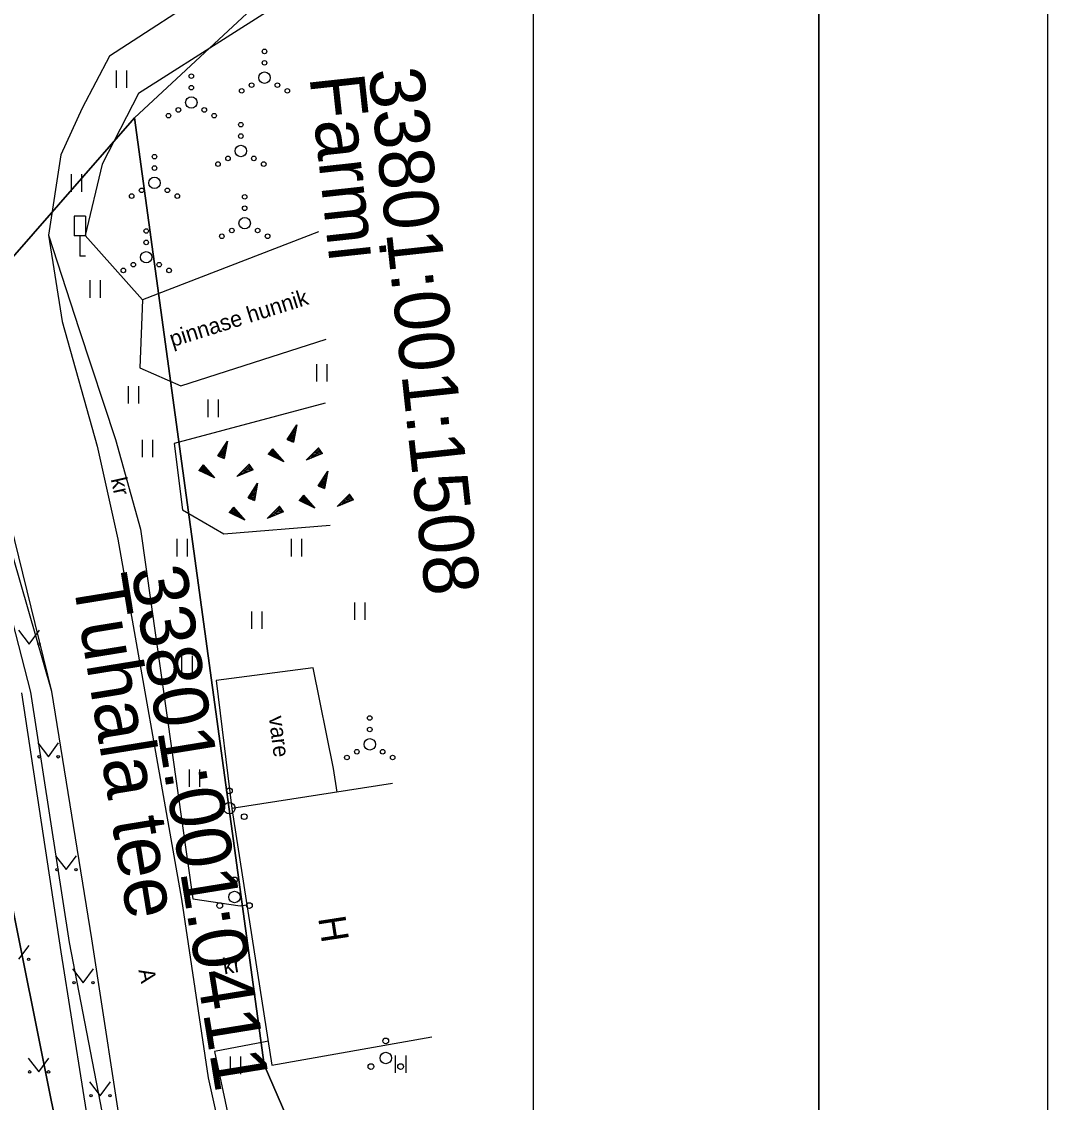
# Model space of a CAD drawing. Extents: x 554947 to 555436, y 6564938 to 6565792.
# Drawn here: x 555348.19 to 555393.07, y 6565480.81 to 6565528.08 of the extents above; entities that cross this region are included whole.
import ezdxf

# ---------------------------------------------------------------- set-up
doc = ezdxf.new("R2010")
doc.units = 0
for name, color, linetype in [('AED', 7, 'Continuous'), ('HALJASTUS', 7, 'Continuous'), ('HOONE', 7, 'Continuous'), ('LIIKLUS', 7, 'Continuous'), ('PIIR', 7, 'Continuous'), ('PR_SIDE', 7, 'Continuous'), ('PUU', 7, 'Continuous'), ('RELJEEF', 7, 'Continuous'), ('TEE', 7, 'Continuous'), ('VORMISTUS_3', 7, 'Continuous')]:
    doc.layers.add(name, color=color, linetype=linetype)

msp = doc.modelspace()

# ---------------------------------------------------------------- linework, layer by layer
at = {"layer": 'AED'}
msp.add_lwpolyline([(555353.187, 6565471.073), (555351.365, 6565478.297), (555349.912, 6565487.399), (555348.203, 6565498.717)], dxfattribs=at)
at = {"layer": 'HALJASTUS'}
for p, q in [((555352.324, 6565525.945), (555352.324, 6565525.183)), ((555352.779, 6565525.945), (555352.779, 6565525.183)), ((555350.36, 6565521.402), (555350.36, 6565520.641)), ((555350.815, 6565521.402), (555350.815, 6565520.641)), ((555351.166, 6565516.766), (555351.166, 6565516.005)), ((555351.621, 6565516.766), (555351.621, 6565516.005)), ((555361.091, 6565513.097), (555361.091, 6565512.335)), ((555361.546, 6565513.097), (555361.546, 6565512.335)), ((555352.843, 6565512.14), (555352.843, 6565511.379)), ((555353.298, 6565512.14), (555353.298, 6565511.379)), ((555356.338, 6565511.545), (555356.338, 6565510.783)), ((555356.793, 6565511.545), (555356.793, 6565510.783)), ((555353.46, 6565509.792), (555353.46, 6565509.031)), ((555353.915, 6565509.792), (555353.915, 6565509.031)), ((555354.98, 6565505.45), (555354.98, 6565504.689)), ((555355.435, 6565505.45), (555355.435, 6565504.689)), ((555359.98, 6565505.45), (555359.98, 6565504.689)), ((555360.435, 6565505.45), (555360.435, 6565504.689)), ((555362.751, 6565502.676), (555362.751, 6565501.915)), ((555363.206, 6565502.676), (555363.206, 6565501.915)), ((555358.242, 6565502.281), (555358.242, 6565501.52)), ((555358.697, 6565502.281), (555358.697, 6565501.52)), ((555348.055, 6565501.461), (555348.518, 6565500.854)), ((555348.518, 6565500.854), (555348.964, 6565501.461)), ((555355.188, 6565500.335), (555355.188, 6565499.574)), ((555355.643, 6565500.335), (555355.643, 6565499.574)), ((555348.895, 6565496.532), (555349.359, 6565495.925)), ((555349.359, 6565495.925), (555349.804, 6565496.532)), ((555355.523, 6565495.364), (555355.523, 6565494.603)), ((555355.978, 6565495.364), (555355.978, 6565494.603)), ((555349.676, 6565491.594), (555350.14, 6565490.987)), ((555350.14, 6565490.987), (555350.585, 6565491.594)), ((555348.068, 6565487.065), (555348.514, 6565487.672)), ((555350.42, 6565486.649), (555350.883, 6565486.043)), ((555350.883, 6565486.043), (555351.329, 6565486.649)), ((555348.474, 6565482.748), (555348.938, 6565482.141)), ((555348.938, 6565482.141), (555349.383, 6565482.748)), ((555357.313, 6565482.807), (555357.313, 6565482.046)), ((555357.768, 6565482.807), (555357.768, 6565482.046)), ((555364.538, 6565482.859), (555364.538, 6565482.097)), ((555364.993, 6565482.859), (555364.993, 6565482.097)), ((555351.163, 6565481.705), (555351.627, 6565481.098)), ((555351.627, 6565481.098), (555352.072, 6565481.705))]:
    msp.add_line(p, q, dxfattribs=at)
for points in [[(555361.377, 6565530.075), (555353.295, 6565524.933), (555351.719, 6565521.845), (555350.973, 6565518.729), (555353.476, 6565515.91)], [(555361.179, 6565518.885), (555353.476, 6565515.91), (555353.355, 6565512.94), (555355.161, 6565512.154), (555361.518, 6565514.185)]]:
    msp.add_lwpolyline(points, dxfattribs=at)
for centre, radius in [((555358.816, 6565526.776), 0.1), ((555358.816, 6565526.276), 0.1), ((555355.614, 6565525.692), 0.1), ((555358.816, 6565525.626), 0.25), ((555355.614, 6565525.192), 0.1), ((555357.816, 6565525.051), 0.1), ((555358.251, 6565525.301), 0.1), ((555359.381, 6565525.301), 0.1), ((555359.816, 6565525.051), 0.1), ((555355.614, 6565524.542), 0.25), ((555355.049, 6565524.217), 0.1), ((555356.179, 6565524.217), 0.1), ((555354.614, 6565523.967), 0.1), ((555356.614, 6565523.967), 0.1), ((555357.781, 6565523.572), 0.1), ((555357.781, 6565523.072), 0.1), ((555357.781, 6565522.422), 0.25), ((555354.001, 6565522.174), 0.1), ((555357.216, 6565522.097), 0.1), ((555358.346, 6565522.097), 0.1), ((555354.001, 6565521.674), 0.1), ((555356.781, 6565521.847), 0.1), ((555358.781, 6565521.847), 0.1), ((555354.001, 6565521.024), 0.25), ((555353.436, 6565520.699), 0.1), ((555354.566, 6565520.699), 0.1), ((555353.001, 6565520.449), 0.1), ((555355.001, 6565520.449), 0.1), ((555357.949, 6565520.416), 0.1), ((555357.949, 6565519.916), 0.1), ((555357.949, 6565519.266), 0.25), ((555353.64, 6565518.922), 0.1), ((555357.384, 6565518.941), 0.1), ((555358.514, 6565518.941), 0.1), ((555353.64, 6565518.422), 0.1), ((555356.949, 6565518.691), 0.1), ((555358.949, 6565518.691), 0.1), ((555353.64, 6565517.772), 0.25), ((555353.075, 6565517.447), 0.1), ((555354.205, 6565517.447), 0.1), ((555352.64, 6565517.197), 0.1), ((555354.64, 6565517.197), 0.1), ((555348.946, 6565500.854), 0.055), ((555363.421, 6565497.618), 0.1), ((555363.421, 6565497.118), 0.1), ((555363.421, 6565496.468), 0.25), ((555362.856, 6565496.143), 0.1), ((555363.986, 6565496.143), 0.1), ((555348.958, 6565495.925), 0.055), ((555349.787, 6565495.925), 0.055), ((555362.421, 6565495.893), 0.1), ((555364.421, 6565495.893), 0.1), ((555349.739, 6565490.987), 0.055), ((555350.567, 6565490.987), 0.055), ((555348.496, 6565487.065), 0.055), ((555350.482, 6565486.043), 0.055), ((555351.311, 6565486.043), 0.055), ((555348.537, 6565482.141), 0.055), ((555349.366, 6565482.141), 0.055), ((555351.225, 6565481.098), 0.055), ((555352.054, 6565481.098), 0.055)]:
    msp.add_circle(centre, radius, dxfattribs=at)
at = {"layer": 'HOONE'}
for points in [[(555361.999, 6565494.379), (555361.839, 6565495.408), (555360.949, 6565499.816), (555356.698, 6565499.263), (555357.386, 6565493.662)], [(555364.41, 6565494.754), (555357.386, 6565493.662), (555359.132, 6565482.428), (555366.132, 6565483.677)]]:
    msp.add_lwpolyline(points, dxfattribs=at)
at = {"layer": 'LIIKLUS'}
for p, q in [((555350.488, 6565519.566), (555350.488, 6565518.716)), ((555350.988, 6565519.566), (555350.488, 6565519.566)), ((555350.988, 6565519.566), (555350.988, 6565518.716)), ((555350.988, 6565518.716), (555350.488, 6565518.716)), ((555350.738, 6565518.716), (555350.738, 6565517.816)), ((555350.988, 6565517.816), (555350.738, 6565517.816))]:
    msp.add_line(p, q, dxfattribs=at)
at = {"layer": 'PIIR'}
for points in [[(555393.069, 6565560.972), (555353.12, 6565523.87), (555343.14, 6565512.46), (555302.6, 6565539.71), (555242.37, 6565583.94), (555179.42, 6565586.32), (555138.98, 6565580.6), (555121.18, 6565602.26), (555116.17, 6565610.5), (555109.96, 6565624.83), (555093.56, 6565628.47), (555079.04, 6565618.4), (555074.13, 6565607.82), (555075.34, 6565593.24), (555091.74, 6565551.94), (555171.91, 6565394.64), (555191.35, 6565341.19), (555195.08, 6565294.61), (555195.28, 6565271.63), (555191.64, 6565237.48)], [(555393.069, 6565456.052), (555368.05, 6565461.11), (555358.8, 6565482.45), (555353.12, 6565523.87), (555393.069, 6565560.972)], [(555393.069, 6565443.872), (555367.06, 6565449.68), (555351.96, 6565468.55), (555343.14, 6565512.46), (555353.12, 6565523.87), (555358.8, 6565482.45), (555368.05, 6565461.11), (555393.069, 6565454.923)]]:
    msp.add_lwpolyline(points, dxfattribs=at)
msp.add_lwpolyline([(555319.44, 6565481.04), (555343.14, 6565512.46), (555351.96, 6565468.55), (555367.06, 6565449.68), (555367.76, 6565374.28), (555361.76, 6565374.07), (555316.84, 6565372.52), (555312.9, 6565433.84), (555323.07, 6565461.26)], close=True, dxfattribs=at)
at = {"layer": 'PR_SIDE'}
msp.add_lwpolyline([(555383.069, 6565448.914), (555372.326, 6565450.448), (555366.015, 6565452.342), (555363.26, 6565453.626), (555360.292, 6565456.785), (555356.82, 6565461.856), (555354.197, 6565468.745), (555353.746, 6565469.93), (555350.28, 6565487.806), (555348.596, 6565498.754), (555346.199, 6565508), (555346.027, 6565508.326), (555343.44, 6565510.968), (555340.158, 6565515.387), (555337.344, 6565518), (555334.369, 6565519.783), (555331.518, 6565521.47), (555329.521, 6565522.71), (555323.586, 6565526.187), (555323.123, 6565526.49), (555319.055, 6565529.304), (555309.687, 6565535.684), (555309.355, 6565535.944), (555304.351, 6565539.861)], dxfattribs=at)
at = {"layer": 'PUU'}
for centre, radius in [((555357.278, 6565494.429), 0.125), ((555357.278, 6565493.679), 0.25), ((555356.628, 6565493.304), 0.125), ((555357.928, 6565493.304), 0.125), ((555357.506, 6565490.54), 0.125), ((555357.506, 6565489.79), 0.25), ((555356.856, 6565489.415), 0.125), ((555358.156, 6565489.415), 0.125), ((555364.12, 6565483.497), 0.125), ((555364.12, 6565482.747), 0.25), ((555363.47, 6565482.372), 0.125), ((555364.77, 6565482.372), 0.125)]:
    msp.add_circle(centre, radius, dxfattribs=at)
at = {"layer": 'RELJEEF'}
for p, q in [((555359.803, 6565509.798), (555360.223, 6565510.438)), ((555360.223, 6565510.438), (555360.083, 6565509.683)), ((555360.198, 6565510.398), (555360.218, 6565510.408)), ((555359.803, 6565509.798), (555360.128, 6565509.938)), ((555359.853, 6565509.873), (555360.138, 6565509.993)), ((555359.903, 6565509.948), (555360.153, 6565510.053)), ((555359.953, 6565510.023), (555360.078, 6565510.078)), ((555360.003, 6565510.098), (555360.173, 6565510.173)), ((555360.053, 6565510.173), (555360.183, 6565510.233)), ((555360.078, 6565510.078), (555360.163, 6565510.113)), ((555360.098, 6565510.248), (555360.198, 6565510.288)), ((555360.148, 6565510.323), (555360.208, 6565510.348)), ((555356.77, 6565509.089), (555357.19, 6565509.729)), ((555356.97, 6565509.389), (555357.14, 6565509.464)), ((555357.02, 6565509.464), (555357.15, 6565509.524)), ((555357.19, 6565509.729), (555357.05, 6565508.974)), ((555357.065, 6565509.539), (555357.165, 6565509.579)), ((555357.115, 6565509.614), (555357.175, 6565509.639)), ((555357.165, 6565509.689), (555357.185, 6565509.699)), ((555359.803, 6565509.798), (555360.083, 6565509.683)), ((555359.803, 6565509.798), (555359.803, 6565509.798)), ((555359.868, 6565509.773), (555360.118, 6565509.878)), ((555359.933, 6565509.743), (555360.108, 6565509.818)), ((555360.003, 6565509.718), (555360.098, 6565509.758)), ((555360.068, 6565509.693), (555360.083, 6565509.698)), ((555360.641, 6565508.892), (555361.181, 6565509.437)), ((555361.351, 6565509.187), (555361.181, 6565509.437)), ((555356.77, 6565509.089), (555357.095, 6565509.229)), ((555356.77, 6565509.089), (555357.05, 6565508.974)), ((555356.77, 6565509.089), (555356.77, 6565509.089)), ((555356.82, 6565509.164), (555357.105, 6565509.284)), ((555356.835, 6565509.064), (555357.085, 6565509.169)), ((555356.87, 6565509.239), (555357.12, 6565509.344)), ((555356.9, 6565509.034), (555357.075, 6565509.109)), ((555356.92, 6565509.314), (555357.045, 6565509.369)), ((555356.97, 6565509.009), (555357.065, 6565509.049)), ((555357.035, 6565508.984), (555357.05, 6565508.989)), ((555357.045, 6565509.369), (555357.13, 6565509.404)), ((555359.162, 6565509.397), (555358.977, 6565509.157)), ((555359.667, 6565508.827), (555358.977, 6565509.157)), ((555358.987, 6565509.172), (555358.992, 6565509.152)), ((555359.032, 6565509.227), (555359.047, 6565509.127)), ((555359.077, 6565509.287), (555359.102, 6565509.102)), ((555359.117, 6565509.342), (555359.152, 6565509.072)), ((555359.162, 6565509.397), (555359.667, 6565508.827)), ((555359.162, 6565509.397), (555359.207, 6565509.047)), ((555359.162, 6565509.397), (555359.162, 6565509.397)), ((555359.222, 6565509.332), (555359.262, 6565509.022)), ((555359.282, 6565509.262), (555359.317, 6565508.997)), ((555359.342, 6565509.197), (555359.357, 6565509.057)), ((555359.357, 6565509.057), (555359.372, 6565508.967)), ((555359.397, 6565509.127), (555359.427, 6565508.942)), ((555359.457, 6565509.062), (555359.477, 6565508.917)), ((555359.517, 6565508.992), (555359.532, 6565508.892)), ((555361.351, 6565509.187), (555360.641, 6565508.892)), ((555360.851, 6565508.977), (555360.746, 6565508.997)), ((555360.931, 6565509.012), (555360.791, 6565509.042)), ((555361.016, 6565509.047), (555360.831, 6565509.082)), ((555360.966, 6565509.107), (555360.876, 6565509.127)), ((555361.181, 6565509.117), (555360.916, 6565509.167)), ((555361.266, 6565509.152), (555360.961, 6565509.212)), ((555361.101, 6565509.082), (555360.966, 6565509.107)), ((555361.351, 6565509.187), (555361.001, 6565509.252)), ((555361.311, 6565509.242), (555361.046, 6565509.297)), ((555361.271, 6565509.302), (555361.086, 6565509.337)), ((555361.231, 6565509.362), (555361.131, 6565509.382)), ((555361.191, 6565509.422), (555361.171, 6565509.422)), ((555361.351, 6565509.187), (555361.351, 6565509.187)), ((555356.128, 6565508.688), (555355.943, 6565508.448)), ((555355.998, 6565508.518), (555356.013, 6565508.418)), ((555356.043, 6565508.578), (555356.068, 6565508.393)), ((555356.083, 6565508.633), (555356.118, 6565508.363)), ((555356.128, 6565508.688), (555356.633, 6565508.118)), ((555356.128, 6565508.688), (555356.173, 6565508.338)), ((555356.128, 6565508.688), (555356.128, 6565508.688)), ((555356.188, 6565508.623), (555356.228, 6565508.313)), ((555356.248, 6565508.553), (555356.283, 6565508.288)), ((555356.308, 6565508.488), (555356.323, 6565508.348)), ((555357.608, 6565508.183), (555358.148, 6565508.728)), ((555358.233, 6565508.443), (555357.928, 6565508.503)), ((555358.318, 6565508.478), (555357.968, 6565508.543)), ((555358.278, 6565508.533), (555358.013, 6565508.588)), ((555358.238, 6565508.593), (555358.053, 6565508.628)), ((555358.198, 6565508.653), (555358.098, 6565508.673)), ((555358.158, 6565508.713), (555358.138, 6565508.713)), ((555358.318, 6565508.478), (555358.148, 6565508.728)), ((555359.577, 6565508.927), (555359.587, 6565508.862)), ((555359.637, 6565508.857), (555359.642, 6565508.837)), ((555360.681, 6565508.907), (555360.666, 6565508.912)), ((555360.766, 6565508.942), (555360.706, 6565508.957)), ((555356.633, 6565508.118), (555355.943, 6565508.448)), ((555355.953, 6565508.463), (555355.958, 6565508.443)), ((555356.323, 6565508.348), (555356.338, 6565508.258)), ((555356.363, 6565508.418), (555356.393, 6565508.233)), ((555356.423, 6565508.353), (555356.443, 6565508.208)), ((555356.483, 6565508.283), (555356.498, 6565508.183)), ((555356.543, 6565508.218), (555356.553, 6565508.153)), ((555356.603, 6565508.148), (555356.608, 6565508.128)), ((555358.318, 6565508.478), (555357.608, 6565508.183)), ((555357.648, 6565508.198), (555357.633, 6565508.203)), ((555357.733, 6565508.233), (555357.673, 6565508.248)), ((555357.818, 6565508.268), (555357.713, 6565508.288)), ((555357.898, 6565508.303), (555357.758, 6565508.333)), ((555357.983, 6565508.338), (555357.798, 6565508.373)), ((555357.933, 6565508.398), (555357.843, 6565508.418)), ((555358.148, 6565508.408), (555357.883, 6565508.458)), ((555358.068, 6565508.373), (555357.933, 6565508.398)), ((555358.318, 6565508.478), (555358.318, 6565508.478)), ((555361.161, 6565507.771), (555361.581, 6565508.411)), ((555361.261, 6565507.921), (555361.511, 6565508.026)), ((555361.311, 6565507.996), (555361.436, 6565508.051)), ((555361.361, 6565508.071), (555361.531, 6565508.146)), ((555361.411, 6565508.146), (555361.541, 6565508.206)), ((555361.436, 6565508.051), (555361.521, 6565508.086)), ((555361.581, 6565508.411), (555361.441, 6565507.656)), ((555361.456, 6565508.221), (555361.556, 6565508.261)), ((555361.506, 6565508.296), (555361.566, 6565508.321)), ((555361.556, 6565508.371), (555361.576, 6565508.381)), ((555358.094, 6565507.249), (555358.514, 6565507.889)), ((555358.294, 6565507.549), (555358.464, 6565507.624)), ((555358.344, 6565507.624), (555358.474, 6565507.684)), ((555358.369, 6565507.529), (555358.454, 6565507.564)), ((555358.514, 6565507.889), (555358.374, 6565507.134)), ((555358.389, 6565507.699), (555358.489, 6565507.739)), ((555358.439, 6565507.774), (555358.499, 6565507.799)), ((555358.489, 6565507.849), (555358.509, 6565507.859)), ((555361.161, 6565507.771), (555361.486, 6565507.911)), ((555361.161, 6565507.771), (555361.441, 6565507.656)), ((555361.161, 6565507.771), (555361.161, 6565507.771)), ((555361.211, 6565507.846), (555361.496, 6565507.966)), ((555361.226, 6565507.746), (555361.476, 6565507.851)), ((555361.291, 6565507.716), (555361.466, 6565507.791)), ((555361.361, 6565507.691), (555361.456, 6565507.731)), ((555361.426, 6565507.666), (555361.441, 6565507.671)), ((555358.094, 6565507.249), (555358.419, 6565507.389)), ((555358.094, 6565507.249), (555358.374, 6565507.134)), ((555358.094, 6565507.249), (555358.094, 6565507.249)), ((555358.144, 6565507.324), (555358.429, 6565507.444)), ((555358.159, 6565507.224), (555358.409, 6565507.329)), ((555358.194, 6565507.399), (555358.444, 6565507.504)), ((555358.224, 6565507.194), (555358.399, 6565507.269)), ((555358.244, 6565507.474), (555358.369, 6565507.529)), ((555358.294, 6565507.169), (555358.389, 6565507.209)), ((555358.359, 6565507.144), (555358.374, 6565507.149)), ((555360.519, 6565507.37), (555360.334, 6565507.13)), ((555361.024, 6565506.8), (555360.334, 6565507.13)), ((555360.344, 6565507.145), (555360.349, 6565507.125)), ((555360.389, 6565507.2), (555360.404, 6565507.1)), ((555360.434, 6565507.26), (555360.459, 6565507.075)), ((555360.474, 6565507.315), (555360.509, 6565507.045)), ((555360.519, 6565507.37), (555361.024, 6565506.8)), ((555360.519, 6565507.37), (555360.564, 6565507.02)), ((555360.519, 6565507.37), (555360.519, 6565507.37)), ((555360.579, 6565507.305), (555360.619, 6565506.995)), ((555360.639, 6565507.235), (555360.674, 6565506.97)), ((555360.699, 6565507.17), (555360.714, 6565507.03)), ((555360.754, 6565507.1), (555360.784, 6565506.915)), ((555361.998, 6565506.865), (555362.538, 6565507.41)), ((555362.708, 6565507.16), (555361.998, 6565506.865)), ((555362.323, 6565507.08), (555362.233, 6565507.1)), ((555362.538, 6565507.09), (555362.273, 6565507.14)), ((555362.623, 6565507.125), (555362.318, 6565507.185)), ((555362.458, 6565507.055), (555362.323, 6565507.08)), ((555362.708, 6565507.16), (555362.358, 6565507.225)), ((555362.668, 6565507.215), (555362.403, 6565507.27)), ((555362.628, 6565507.275), (555362.443, 6565507.31)), ((555362.588, 6565507.335), (555362.488, 6565507.355)), ((555362.548, 6565507.395), (555362.528, 6565507.395)), ((555362.708, 6565507.16), (555362.538, 6565507.41)), ((555362.708, 6565507.16), (555362.708, 6565507.16)), ((555357.452, 6565506.849), (555357.267, 6565506.609)), ((555357.957, 6565506.279), (555357.267, 6565506.609)), ((555357.277, 6565506.624), (555357.282, 6565506.604)), ((555357.322, 6565506.679), (555357.337, 6565506.579)), ((555357.367, 6565506.739), (555357.392, 6565506.554)), ((555357.407, 6565506.794), (555357.442, 6565506.524)), ((555357.452, 6565506.849), (555357.957, 6565506.279)), ((555357.452, 6565506.849), (555357.497, 6565506.499)), ((555357.452, 6565506.849), (555357.452, 6565506.849)), ((555357.512, 6565506.784), (555357.552, 6565506.474)), ((555357.572, 6565506.714), (555357.607, 6565506.449)), ((555357.632, 6565506.649), (555357.647, 6565506.509)), ((555358.932, 6565506.344), (555359.472, 6565506.889)), ((555359.642, 6565506.639), (555358.932, 6565506.344)), ((555359.472, 6565506.569), (555359.207, 6565506.619)), ((555359.557, 6565506.604), (555359.252, 6565506.664)), ((555359.642, 6565506.639), (555359.292, 6565506.704)), ((555359.602, 6565506.694), (555359.337, 6565506.749)), ((555359.562, 6565506.754), (555359.377, 6565506.789)), ((555359.522, 6565506.814), (555359.422, 6565506.834)), ((555359.482, 6565506.874), (555359.462, 6565506.874)), ((555359.642, 6565506.639), (555359.472, 6565506.889)), ((555359.642, 6565506.639), (555359.642, 6565506.639)), ((555360.714, 6565507.03), (555360.729, 6565506.94)), ((555360.814, 6565507.035), (555360.834, 6565506.89)), ((555360.874, 6565506.965), (555360.889, 6565506.865)), ((555360.934, 6565506.9), (555360.944, 6565506.835)), ((555360.994, 6565506.83), (555360.999, 6565506.81)), ((555362.038, 6565506.88), (555362.023, 6565506.885)), ((555362.123, 6565506.915), (555362.063, 6565506.93)), ((555362.208, 6565506.95), (555362.103, 6565506.97)), ((555362.288, 6565506.985), (555362.148, 6565507.015)), ((555362.373, 6565507.02), (555362.188, 6565507.055)), ((555357.647, 6565506.509), (555357.662, 6565506.419)), ((555357.687, 6565506.579), (555357.717, 6565506.394)), ((555357.747, 6565506.514), (555357.767, 6565506.369)), ((555357.807, 6565506.444), (555357.822, 6565506.344)), ((555357.867, 6565506.379), (555357.877, 6565506.314)), ((555357.927, 6565506.309), (555357.932, 6565506.289)), ((555358.972, 6565506.359), (555358.957, 6565506.364)), ((555359.057, 6565506.394), (555358.997, 6565506.409)), ((555359.142, 6565506.429), (555359.037, 6565506.449)), ((555359.222, 6565506.464), (555359.082, 6565506.494)), ((555359.307, 6565506.499), (555359.122, 6565506.534)), ((555359.257, 6565506.559), (555359.167, 6565506.579)), ((555359.392, 6565506.534), (555359.257, 6565506.559))]:
    msp.add_line(p, q, dxfattribs=at)
msp.add_lwpolyline([(555361.463, 6565511.386), (555354.86, 6565509.627), (555355.225, 6565506.727), (555357.042, 6565505.67), (555361.69, 6565506.056)], dxfattribs=at)
at = {"layer": 'TEE'}
for points in [[(555360.017, 6565532.032), (555356.722, 6565529.611), (555352.039, 6565526.571), (555350.841, 6565524.289), (555349.902, 6565522.246), (555349.37, 6565518.742), (555349.968, 6565514.969), (555351.498, 6565509.514), (555352.399, 6565505.44), (555355.185, 6565489.693), (555356.356, 6565481.874), (555358.536, 6565472.027), (555360.203, 6565467.288), (555362.127, 6565463.387), (555364.998, 6565459.532), (555367.923, 6565457.754), (555371.76, 6565456.513), (555378.11, 6565454.853), (555393.069, 6565452.684)], [(555393.069, 6565448.493), (555392.904, 6565448.521), (555377.792, 6565450.52), (555372.547, 6565451.424), (555369.187, 6565452.37), (555366.443, 6565453.255), (555364.23, 6565454.662), (555361.13, 6565458.083), (555357.411, 6565463.749), (555354.693, 6565470.258), (555353.748, 6565473.64), (555352.733, 6565478.362), (555351.267, 6565487.961), (555349.516, 6565498.784), (555347.141, 6565508.358), (555345.332, 6565511.802), (555341.773, 6565516.752), (555338.53, 6565519.62), (555330.669, 6565524.333), (555325.029, 6565527.171), (555324.447, 6565527.997), (555320.204, 6565530.941)], [(555349.516, 6565498.784), (555346.789, 6565508.206), (555344.895, 6565511.389), (555341.304, 6565516.362), (555338.53, 6565519.62)], [(555349.37, 6565518.742), (555350.702, 6565514.609), (555352.294, 6565509.808), (555353.389, 6565505.873), (555355.685, 6565489.704), (555357.745, 6565489.405), (555358.04, 6565489.451)], [(555358.969, 6565483.478), (555358.843, 6565483.458), (555356.63, 6565483.037), (555358.965, 6565472.102), (555360.762, 6565467.568), (555362.536, 6565463.692), (555365.5, 6565460.084), (555367.923, 6565457.754)]]:
    msp.add_lwpolyline(points, dxfattribs=at)
at = {"layer": 'VORMISTUS_3'}
for points in [[(555183.069, 6565701.752), (555393.069, 6565701.752), (555393.069, 6565404.752), (555183.069, 6565404.752)], [(555193.069, 6565415.752), (555383.069, 6565415.752), (555383.069, 6565690.752), (555193.069, 6565690.752)], [(555193.069, 6565690.752), (555383.069, 6565690.752), (555383.069, 6565415.752), (555193.069, 6565415.752)], [(555370.569, 6565441.752), (555205.569, 6565441.752), (555205.569, 6565651.752), (555370.569, 6565651.752)]]:
    msp.add_lwpolyline(points, close=True, dxfattribs=at)

# ---------------------------------------------------------------- texts
at = {"layer": 'HALJASTUS'}
msp.add_text('pinnase hunnik', height=0.7, rotation=17.4286, dxfattribs=at).set_placement((555354.784, 6565513.837))
at = {"layer": 'HOONE'}
for s, height, rotation, p in [('vare', 0.7, 277.0041, (555359.004, 6565497.676)), ('H', 1.2, 278.8351, (555361.157, 6565488.875))]:
    msp.add_text(s, height=height, rotation=rotation, dxfattribs=at).set_placement(p)
at = {"layer": 'PIIR'}
for s, rotation, p in [('33801:001:1508', 276.1984, (555363.362, 6565525.96)), ('Farmi', 276.1984, (555360.777, 6565525.679)), ('33801:001:0411', 279.2075, (555352.979, 6565504.107)), ('Tuhala tee', 279.2075, (555350.412, 6565503.691))]:
    msp.add_text(s, height=2.4, rotation=rotation, dxfattribs=at).set_placement(p)
at = {"layer": 'TEE'}
for s, rotation, p in [('kr', 282.4255, (555352.084, 6565508.068)), ('kr', 9.7665, (555357.052, 6565486.401)), ('A', 282.0011, (555353.293, 6565486.59))]:
    msp.add_text(s, height=0.7, rotation=rotation, dxfattribs=at).set_placement(p)

doc.saveas('drawing.dxf')
